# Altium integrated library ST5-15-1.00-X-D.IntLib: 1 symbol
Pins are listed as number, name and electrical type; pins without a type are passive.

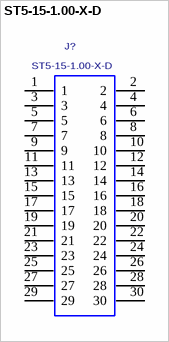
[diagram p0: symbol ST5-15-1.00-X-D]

## ST5-15-1.00-X-D
designator J?
0.5mm TERMINAL STRIP ASSEMBLY, 30 PINS.; MANUFACTURER: SAMTEC
footprint ST5-15-1.00-X-D
footprint ST5-15-1.00-X-D
pins: 1, 2, 3, 4, 5, 6, 7, 8, 9, 10, 11, 12, 13, 14, 15, 16, 17, 18, 19, 20, 21, 22, 23, 24, 25, 26, 27, 28, 29, 30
